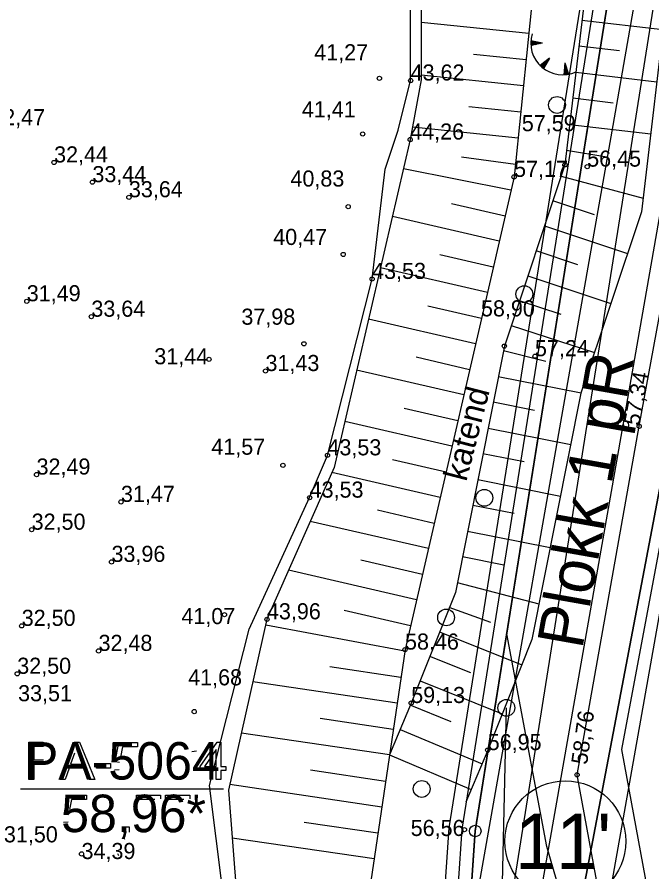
# Model space of a CAD drawing. Extents: x 700746 to 706058, y 6570320 to 6580460.
# Drawn here: x 703241.9 to 703338.5, y 6576222.3 to 6576352.4 of the extents above; entities that cross this region are included whole.
import ezdxf

# ---------------------------------------------------------------- set-up
doc = ezdxf.new("R2010")
doc.units = 0
for name, color, linetype in [('GEOLPUNKT', 7, 'Continuous'), ('HALJASTUS', 7, 'Continuous'), ('illumineerimisjooned', 7, 'Continuous'), ('Kaitsevöönd', 7, 'Continuous'), ('kataster', 7, 'Continuous'), ('KORGUS-EH2000', 7, 'Continuous'), ('KPOHULIIN', 7, 'Continuous'), ('PIIR', 7, 'Continuous'), ('Plokid', 7, 'Continuous'), ('POST', 7, 'Continuous'), ('RELJEEF', 7, 'Continuous'), ('TEE', 7, 'Continuous'), ('Tmaad_maeeraldised_kehtivad', 7, 'Continuous'), ('VEEKOGU', 7, 'Continuous'), ('VTRASS', 7, 'Continuous'), ('VWX2_MV_PLOKK', 7, 'Continuous')]:
    doc.layers.add(name, color=color, linetype=linetype)

msp = doc.modelspace()

# ---------------------------------------------------------------- linework, layer by layer
at = {"layer": 'GEOLPUNKT'}
msp.add_line((703242.38, 6576234.95), (703273.29, 6576234.95), dxfattribs=at)
msp.add_line((703242.38, 6576234.95), (703273.29, 6576234.95), dxfattribs=at)
for points in [[(703243.66, 6576236.35), (703243.66, 6576242.05), (703245.81, 6576242.05)], [(703248.35, 6576236.35), (703250.54, 6576242.05), (703251.36, 6576242.05), (703253.69, 6576236.35), (703252.83, 6576236.35), (703252.17, 6576238.07), (703249.78, 6576238.07), (703249.15, 6576236.35), (703248.35, 6576236.35)], [(703257.44, 6576238.96), (703256.78, 6576239.05), (703257.33, 6576241.98), (703260.17, 6576241.98), (703260.17, 6576241.31), (703257.89, 6576241.31), (703257.59, 6576239.78)], [(703272.18, 6576236.35), (703272.18, 6576237.71), (703269.71, 6576237.71), (703269.71, 6576238.36), (703272.3, 6576242.05), (703272.88, 6576242.05), (703272.88, 6576238.36), (703273.65, 6576238.36), (703273.65, 6576237.71), (703272.88, 6576237.71), (703272.88, 6576236.35), (703272.18, 6576236.35)], [(703245.88, 6576241.38), (703244.42, 6576241.38), (703244.42, 6576239.34)], [(703269.15, 6576240.65), (703268.45, 6576240.59)], [(703272.18, 6576238.36), (703272.18, 6576240.93), (703270.39, 6576238.36), (703272.18, 6576238.36)], [(703244.42, 6576239.34), (703245.89, 6576239.34)], [(703250.62, 6576240.36), (703250, 6576238.69)], [(703250, 6576238.69), (703251.93, 6576238.69), (703251.33, 6576240.27)], [(703245.88, 6576238.67), (703244.42, 6576238.67), (703244.42, 6576236.35), (703243.66, 6576236.35)], [(703253.92, 6576238.06), (703253.92, 6576238.77), (703256.08, 6576238.77), (703256.08, 6576238.06), (703253.92, 6576238.06)], [(703256.66, 6576237.84), (703257.39, 6576237.9)], [(703249.68, 6576230.96), (703249.02, 6576231.05), (703249.58, 6576233.98), (703252.41, 6576233.98), (703252.41, 6576233.31), (703250.14, 6576233.31), (703249.83, 6576231.78)], [(703260.01, 6576233.3), (703260.01, 6576233.98), (703263.7, 6576233.98), (703263.7, 6576233.43)], [(703262.8, 6576233.3), (703260.01, 6576233.3)], [(703264.44, 6576233.3), (703264.44, 6576233.98), (703268.13, 6576233.98), (703268.13, 6576233.43)], [(703267.23, 6576233.3), (703264.44, 6576233.3)], [(703248.9, 6576229.84), (703249.63, 6576229.9)], [(703258.13, 6576228.35), (703258.13, 6576229.14), (703258.93, 6576229.14), (703258.93, 6576228.35)], [(703258.53, 6576228.35), (703258.13, 6576228.35)], [(703261.53, 6576228.35), (703260.81, 6576228.35)], [(703265.95, 6576228.35), (703265.23, 6576228.35)], [(703258.28, 6576227.22), (703258.08, 6576227.52)], [(703257.36, 6576224.76), (703257.17, 6576225.06)]]:
    msp.add_lwpolyline(points, dxfattribs=at)
at = {"layer": 'HALJASTUS'}
for centre in [(703324.05, 6576339.03), (703319.07, 6576310.24), (703312.98, 6576279.23), (703307.16, 6576261.03), (703316.34, 6576247.26), (703303.45, 6576234.92)]:
    msp.add_circle(centre, 1.28, dxfattribs=at)
at = {"layer": 'illumineerimisjooned'}
msp.add_lwpolyline([(703275.45, 6577071.68), (703358.03, 6576531.93), (703309.57, 6576228.79), (703291.69, 6575965.8), (703292.02, 6575933.77), (703296.8, 6575575.06), (702854, 6575511.22), (702839.23, 6575620.77), (702850.34, 6575977.31), (702784.78, 6576064.06), (702784.62, 6576095.83), (702844.43, 6576209.85), (702855.46, 6576267.3), (702846.53, 6576489.41), (702878.89, 6576547.09), (702976.89, 6576643.26), (702915.33, 6577059.56)], dxfattribs=at)
at = {"layer": 'Kaitsevöönd'}
for points in [[(703294.41, 6577068.37), (703355.65, 6576672.76), (703381.7, 6576504.41), (703381.65, 6576500.93), (703378.17, 6576481.28), (703346.05, 6576297.71), (703328.2, 6576197.08), (703364.66, 6576062.16)], [(703344.9, 6576060.57), (703308.07, 6576196.97), (703332.57, 6576335.91), (703361.8, 6576503.07), (703344.23, 6576615.3), (703332.06, 6576694.74), (703304.44, 6576872.64)]]:
    msp.add_lwpolyline(points, dxfattribs=at)
at = {"layer": 'kataster'}
msp.add_lwpolyline([(702852.27, 6575508.89), (702837.26, 6575620.73), (702848.38, 6575976.59), (702782.85, 6576063.35), (702782.57, 6576096.37), (702842.53, 6576210.56), (702853.4, 6576267.5), (702844.46, 6576489.93), (702877.29, 6576548.25), (702974.72, 6576643.9), (702913.57, 6577058.07), (702784.04, 6577102.84), (702746.48, 6577248.7), (702719.69, 6577297.36), (702713.81, 6577334.91), (703089.87, 6577211.79), (703231.53, 6577106.55), (703277.36, 6577072.83), (703360.09, 6576531.99), (703311.6, 6576228.52), (703293.62, 6575965.66), (703298.84, 6575573.29)], close=True, dxfattribs=at)
msp.add_lwpolyline([(703361.97, 6576073.22), (703340.19, 6576155.31), (703330.14, 6576199.75), (703322.48, 6576226.18), (703316.39, 6576258.52), (703360.09, 6576531.99), (703277.36, 6577072.83)], dxfattribs=at)
at = {"layer": 'KORGUS-EH2000'}
for centre in [(703297.01, 6576343.08), (703301.76, 6576342.75), (703294.47, 6576334.62), (703301.7, 6576333.77), (703247.49, 6576330.28), (703325.25, 6576329.91), (703328.64, 6576329.64), (703317.51, 6576328.08), (703253.32, 6576327.28), (703258.88, 6576324.98), (703292.26, 6576323.56), (703291.5, 6576316.28), (703295.9, 6576312.55), (703243.33, 6576309.15), (703253.16, 6576306.8), (703285.52, 6576302.68), (703316.03, 6576302.32), (703271.07, 6576300.31), (703320.69, 6576300.79), (703279.67, 6576298.53), (703336.56, 6576290.12), (703289.1, 6576285.7), (703282.32, 6576284.18), (703244.82, 6576282.77), (703257.67, 6576278.61), (703286.39, 6576279.26), (703244.07, 6576274.38), (703256.23, 6576269.48), (703273.43, 6576261.45), (703279.89, 6576260.74), (703242.56, 6576259.74), (703254.26, 6576255.93), (703300.91, 6576256.13), (703241.88, 6576252.45), (703301.85, 6576248), (703268.82, 6576246.7), (703313.5, 6576240.83), (703327.1, 6576237.07), (703309.96, 6576228.72), (703251.67, 6576225.03)]:
    msp.add_circle(centre, 0.32, dxfattribs=at)
at = {"layer": 'KPOHULIIN'}
msp.add_lwpolyline([(703335.89, 6576129.69), (703317.61, 6576196.56), (703334.12, 6576290.28), (703354.88, 6576408.94), (703371.63, 6576502.97), (703360.78, 6576573.5), (703348.19, 6576656.26), (703310.09, 6576902.12)], dxfattribs=at)
at = {"layer": 'PIIR'}
for centre, radius in [((703325.32, 6576226.96), 9.2), ((703311.6, 6576228.52), 0.88)]:
    msp.add_circle(centre, radius, dxfattribs=at)
at = {"layer": 'Plokid'}
for points in [[(703290.64, 6576959.22), (703356.01, 6576531.94), (703307.59, 6576229.01), (703289.69, 6575965.85), (703290.02, 6575933.75), (703291.51, 6575829.64), (703294.32, 6575609.52), (703294.77, 6575576.79), (703154.76, 6575556.6), (703019.06, 6575536.97), (703053.36, 6575698.14), (703145.59, 6575981.92), (703123.04, 6576234.88), (703120.61, 6576749.6), (703011.59, 6576989.47), (702968.34, 6577084.63), (702917.3, 6577059.88)], [(703294.02, 6575933.8), (703311.73, 6576015.89), (703324.97, 6576203.4), (703382.07, 6576503.63), (703406.89, 6576414.25), (703421.79, 6576214.16), (703443.8, 6575689.35), (703467.14, 6575602.46), (703308.25, 6575608.58), (703295.51, 6575829.03)]]:
    msp.add_lwpolyline(points, dxfattribs=at)
at = {"layer": 'POST'}
for radius in [0.8, 0.0747]:
    msp.add_circle((703334.12, 6576290.28), radius, dxfattribs=at)
at = {"layer": 'RELJEEF'}
for p, q in [((703319.75, 6576349.91), (703303.36, 6576351.59)), ((703327.85, 6576351.96), (703340.18, 6576350.51)), ((703320.04, 6576348.6), (703320.26, 6576348.77)), ((703320.04, 6576348.49), (703320.36, 6576348.75)), ((703320.04, 6576348.39), (703320.46, 6576348.73)), ((703320.04, 6576348.29), (703320.57, 6576348.71)), ((703321.83, 6576348.46), (703320.05, 6576348.81)), ((703320.05, 6576348.7), (703320.15, 6576348.79)), ((703320.05, 6576348.19), (703320.67, 6576348.69)), ((703320.09, 6576348.12), (703320.77, 6576348.67)), ((703320.26, 6576348.15), (703320.88, 6576348.65)), ((703320.43, 6576348.19), (703320.98, 6576348.63)), ((703320.6, 6576348.22), (703321.08, 6576348.61)), ((703320.77, 6576348.25), (703321.18, 6576348.59)), ((703320.94, 6576348.29), (703321.29, 6576348.57)), ((703321.83, 6576348.46), (703320.05, 6576348.11)), ((703321.11, 6576348.32), (703321.39, 6576348.55)), ((703321.27, 6576348.35), (703321.49, 6576348.53)), ((703321.44, 6576348.39), (703321.6, 6576348.51)), ((703321.61, 6576348.42), (703321.7, 6576348.49)), ((703333.55, 6576347.27), (703327.38, 6576347.99)), ((703311.35, 6576346.75), (703319.34, 6576345.93)), ((703322.9, 6576346.16), (703321.47, 6576345.03)), ((703322.9, 6576346.16), (703322, 6576344.58)), ((703322.7, 6576345.81), (703322.71, 6576346.01)), ((703322.79, 6576345.96), (703322.79, 6576346.07)), ((703321.55, 6576344.96), (703321.55, 6576345.09)), ((703321.63, 6576344.89), (703321.64, 6576345.16)), ((703321.7, 6576344.82), (703321.72, 6576345.23)), ((703321.78, 6576344.75), (703321.8, 6576345.29)), ((703321.86, 6576344.69), (703321.88, 6576345.36)), ((703321.94, 6576344.63), (703321.97, 6576345.42)), ((703322.02, 6576344.61), (703322.05, 6576345.49)), ((703322.1, 6576344.76), (703322.13, 6576345.55)), ((703322.19, 6576344.91), (703322.21, 6576345.62)), ((703322.27, 6576345.06), (703322.3, 6576345.68)), ((703322.36, 6576345.21), (703322.38, 6576345.75)), ((703322.44, 6576345.36), (703322.46, 6576345.81)), ((703322.53, 6576345.51), (703322.54, 6576345.88)), ((703322.62, 6576345.66), (703322.62, 6576345.94)), ((703325.24, 6576345.44), (703325.1, 6576343.63)), ((703325.62, 6576344.24), (703325.18, 6576344.68)), ((703325.57, 6576344.4), (703325.19, 6576344.78)), ((703325.52, 6576344.57), (703325.2, 6576344.89)), ((703325.41, 6576344.9), (703325.21, 6576345.1)), ((703325.47, 6576344.73), (703325.21, 6576344.99)), ((703325.36, 6576345.06), (703325.22, 6576345.2)), ((703325.31, 6576345.23), (703325.23, 6576345.31)), ((703325.24, 6576345.44), (703325.79, 6576343.71)), ((703318.93, 6576341.95), (703303.35, 6576343.55)), ((703325.21, 6576343.64), (703325.11, 6576343.73)), ((703325.31, 6576343.65), (703325.12, 6576343.84)), ((703325.42, 6576343.66), (703325.13, 6576343.94)), ((703325.62, 6576343.68), (703325.14, 6576344.15)), ((703325.52, 6576343.67), (703325.14, 6576344.05)), ((703325.72, 6576343.7), (703325.15, 6576344.26)), ((703325.78, 6576343.75), (703325.16, 6576344.36)), ((703325.68, 6576344.08), (703325.17, 6576344.57)), ((703325.73, 6576343.91), (703325.17, 6576344.47)), ((703326.92, 6576344.02), (703339.24, 6576342.57)), ((703332.61, 6576339.32), (703326.45, 6576340.05)), ((703310.64, 6576338.78), (703318.52, 6576337.97)), ((703318.11, 6576333.99), (703302.04, 6576335.64)), ((703325.98, 6576336.07), (703338.31, 6576334.62)), ((703331.64, 6576331.09), (703325.51, 6576332.1)), ((703309.52, 6576331.12), (703317.71, 6576330.01)), ((703317.04, 6576326.07), (703300.67, 6576329.33)), ((703324.69, 6576328.21), (703337.15, 6576324.82)), ((703308.01, 6576324.05), (703316.14, 6576322.18)), ((703329.74, 6576322.3), (703323.42, 6576324.42)), ((703315.25, 6576318.28), (703298.98, 6576322.03)), ((703322.15, 6576320.62), (703334.79, 6576316.4)), ((703306.21, 6576316.26), (703314.35, 6576314.38)), ((703327.2, 6576314.72), (703320.88, 6576316.83)), ((703313.45, 6576310.48), (703297.17, 6576314.24)), ((703319.62, 6576313.03), (703332.25, 6576308.81)), ((703304.4, 6576308.46), (703312.55, 6576306.59)), ((703324.67, 6576307.13), (703318.35, 6576309.24)), ((703311.65, 6576302.69), (703295.35, 6576306.45)), ((703317.08, 6576305.45), (703329.76, 6576301.36)), ((703302.6, 6576300.67), (703310.75, 6576298.79)), ((703322.33, 6576300), (703315.9, 6576301.63)), ((703309.85, 6576294.89), (703293.54, 6576298.65)), ((703315.11, 6576297.71), (703327.7, 6576295.2)), ((703300.8, 6576292.88), (703308.95, 6576291)), ((703320.62, 6576292.53), (703314.33, 6576293.79)), ((703308.05, 6576287.1), (703291.73, 6576290.86)), ((703313.55, 6576289.86), (703326.13, 6576287.36)), ((703298.99, 6576285.08), (703307.15, 6576283.2)), ((703319.06, 6576284.69), (703312.77, 6576285.94)), ((703306.25, 6576279.3), (703289.77, 6576283.1)), ((703311.99, 6576282.02), (703324.57, 6576279.51)), ((703296.74, 6576277.39), (703305.36, 6576275.4)), ((703317.5, 6576276.84), (703311.21, 6576278.09)), ((703304.46, 6576271.51), (703286.48, 6576275.65)), ((703310.43, 6576274.17), (703323.01, 6576271.67)), ((703294.2, 6576269.77), (703303.56, 6576267.61)), ((703315.94, 6576268.99), (703309.65, 6576270.25)), ((703302.66, 6576263.71), (703283.19, 6576268.2)), ((703308.87, 6576266.32), (703321.3, 6576263.11)), ((703291.64, 6576262.12), (703301.76, 6576259.81)), ((703313.97, 6576260.26), (703307.65, 6576262.53)), ((703300.88, 6576255.91), (703279.7, 6576259.87)), ((703306.17, 6576258.82), (703318.69, 6576253.82)), ((703310.94, 6576252.6), (703304.68, 6576255.1)), ((703289.46, 6576253.56), (703300.29, 6576251.96)), ((703299.7, 6576248), (703277.76, 6576251.25)), ((703303.2, 6576251.39), (703315.71, 6576246.38)), ((703307.95, 6576245.12), (703301.71, 6576247.67)), ((703288, 6576245.69), (703299.12, 6576244.04)), ((703298.53, 6576240.09), (703276, 6576243.42)), ((703300.17, 6576243.98), (703312.63, 6576238.76)), ((703298.53, 6576240.09), (703311, 6576234.86)), ((703286.54, 6576237.82), (703297.95, 6576236.13)), ((703297.36, 6576232.17), (703274.25, 6576235.6)), ((703285.54, 6576229.88), (703296.77, 6576228.22)), ((703296.19, 6576224.26), (703274.62, 6576227.45))]:
    msp.add_line(p, q, dxfattribs=at)
for points in [[(703294.98, 6576976.89), (703298.01, 6576952.03), (703308.39, 6576903.66), (703310.22, 6576881.63), (703320.05, 6576759.49), (703327.51, 6576726.85), (703331.13, 6576688.4), (703329.02, 6576656.14), (703332.85, 6576644.87), (703338.24, 6576624.53), (703339.69, 6576609.71), (703342.98, 6576573.75), (703350.64, 6576557.99), (703360.73, 6576522.36), (703358.27, 6576513.58), (703356.22, 6576500.08), (703348.18, 6576445.4), (703346.58, 6576371.38), (703340.93, 6576356.93), (703336.91, 6576322.74), (703327.68, 6576295.15), (703320.22, 6576257.66), (703313.5, 6576240.83), (703310.18, 6576232.92)], [(703287.76, 6576969.22), (703301.66, 6576878.37), (703308.4, 6576766.66), (703315.86, 6576734.02), (703319.48, 6576695.57), (703324.84, 6576668.62), (703325.06, 6576655.25), (703326.59, 6576631.7), (703333, 6576614.8), (703334.36, 6576592.7), (703343.18, 6576565.16), (703350.63, 6576529.53), (703350.13, 6576518.58), (703344.56, 6576507.25), (703336.53, 6576452.57), (703334.93, 6576378.55), (703329.28, 6576364.1), (703325.25, 6576329.91), (703316.03, 6576302.32), (703308.57, 6576264.82), (703301.85, 6576248), (703298.53, 6576240.09)], [(703290.63, 6576796.53), (703294.18, 6576752.74), (703301.26, 6576735.92), (703310.06, 6576699.51), (703308, 6576689.73), (703309.22, 6576677.55), (703319.19, 6576654.75), (703329.82, 6576561.84), (703330.05, 6576553.02), (703327.91, 6576515.52), (703314.12, 6576455.74), (703313.17, 6576416.87), (703317.14, 6576393.59), (703321.81, 6576369.95), (703317.51, 6576328.08), (703300.91, 6576256.13), (703281.53, 6576125.34), (703279.97, 6576118.46), (703265.55, 6576092.54), (703268.13, 6576079.38)], [(703303.38, 6576364.56), (703303.35, 6576342.85), (703301.7, 6576333.77), (703290.11, 6576283.87), (703279.89, 6576260.74), (703274.06, 6576234.76), (703275.32, 6576218.35), (703275.49, 6576205.75), (703269.41, 6576189.26), (703271.94, 6576176.58), (703267.72, 6576162.54), (703268.7, 6576147.32), (703268.71, 6576122.58), (703265.25, 6576111.59), (703260.9, 6576100.04), (703247.69, 6576093.18), (703243.06, 6576086.17)], [(703343.84, 6576081.11), (703335.7, 6576108.2), (703330.71, 6576134.71), (703326.75, 6576152.5), (703322.22, 6576165.18), (703315.6, 6576173.43), (703312.69, 6576179.01), (703314.2, 6576192.38), (703315.77, 6576220.64), (703316.34, 6576247.26)]]:
    msp.add_lwpolyline(points, dxfattribs=at)
msp.add_arc((703324.88, 6576348.47), 4.84, 163.4234, 295.1745, dxfattribs=at)
at = {"layer": 'TEE'}
for points in [[(703352.19, 6576141.74), (703333.89, 6576240.91), (703343.28, 6576291), (703349.94, 6576325.8), (703355.47, 6576356.51), (703364.51, 6576409.39), (703371.49, 6576445.79), (703377.05, 6576478.47), (703380.32, 6576501.7), (703378.7, 6576535.4), (703372.61, 6576579.28), (703366.54, 6576617.95), (703359.6, 6576660.21), (703326.86, 6576887.21), (703316.48, 6576960.36), (703310.76, 6576994.71), (703303.15, 6577040.42), (703296.06, 6577071.1), (703290.16, 6577081.59), (703186.34, 6577164.98)], [(703345.4, 6576137.9), (703327.1, 6576237.07), (703336.56, 6576290.12), (703343.25, 6576326.51), (703348.81, 6576358.13), (703358.18, 6576409.8), (703364.65, 6576448.18), (703369.91, 6576476.49), (703373.71, 6576502.52), (703371.54, 6576534.25), (703365.82, 6576575.44), (703359.75, 6576614.11), (703352.81, 6576656.37), (703320.07, 6576883.37), (703309.69, 6576956.52), (703303.97, 6576990.87), (703296.36, 6577036.58), (703289.27, 6577067.26), (703283.37, 6577077.75), (703179.55, 6577161.14)]]:
    msp.add_lwpolyline(points, dxfattribs=at)
at = {"layer": 'Tmaad_maeeraldised_kehtivad'}
msp.add_lwpolyline([(703277.3, 6577072.8), (703360.06, 6576531.93), (703311.56, 6576228.56), (703293.69, 6575965.74), (703294.02, 6575933.8), (703298.82, 6575573.33), (702852.29, 6575508.95), (702837.23, 6575620.66), (702848.32, 6575976.66), (702782.78, 6576063.39), (702782.61, 6576096.32), (702842.53, 6576210.52), (702853.45, 6576267.45), (702844.51, 6576489.89), (702877.28, 6576548.31), (702974.76, 6576643.97), (702913.53, 6577058.07)], dxfattribs=at)
at = {"layer": 'VEEKOGU'}
msp.add_lwpolyline([(703242.36, 6576086.56), (703246.24, 6576093.9), (703260.25, 6576102.13), (703264.13, 6576113.28), (703267, 6576122.75), (703266.58, 6576147.78), (703264.89, 6576162.72), (703269.88, 6576177.55), (703266.92, 6576189.55), (703273.59, 6576206.89), (703273.17, 6576219.29), (703271.14, 6576235.47), (703277.19, 6576259.24), (703286.39, 6576279.26), (703289.1, 6576285.7), (703295.9, 6576312.55), (703297.89, 6576329.27), (703299.86, 6576335.18), (703301.76, 6576342.75), (703301.78, 6576365.92)], dxfattribs=at)
msp.add_lwpolyline([(703242.36, 6576086.56), (703246.24, 6576093.9), (703260.25, 6576102.13), (703264.13, 6576113.28), (703267, 6576122.75), (703266.58, 6576147.78), (703264.89, 6576162.72), (703269.88, 6576177.55), (703266.92, 6576189.55), (703273.59, 6576206.89), (703273.17, 6576219.29), (703271.14, 6576235.47), (703277.19, 6576259.24), (703286.39, 6576279.26), (703289.1, 6576285.7), (703295.9, 6576312.55), (703297.89, 6576329.27), (703299.86, 6576335.18), (703301.76, 6576342.75), (703301.78, 6576365.92)], dxfattribs=at)
at = {"layer": 'VTRASS'}
msp.add_lwpolyline([(703383.92, 6576537.61), (703365.97, 6576507.97), (703351.39, 6576433.02), (703345.21, 6576395.16), (703316.4, 6576213.76)], dxfattribs=at)
at = {"layer": 'VWX2_MV_PLOKK'}
for points in [[(703044.07, 6577449.05), (703125.37, 6577441.7), (703167.08, 6577172.26), (703170.22, 6577152.1), (703231.53, 6577106.55), (703277.36, 6577072.83), (703360.09, 6576531.99), (703311.6, 6576228.52), (703293.62, 6575965.66), (703294.04, 6575933.77), (703295.43, 6575829.7), (703298.36, 6575609.6), (703298.84, 6575573.29), (703155.29, 6575552.59), (703145.59, 6575981.92), (703123.04, 6576234.88), (703120.61, 6576749.6), (703011.59, 6576989.47), (703015.74, 6577110.88), (702996.73, 6577210.32)], [(703170.54, 6577151.86), (703296.17, 6577067.83), (703382.07, 6576503.63), (703324.97, 6576203.4), (703311.73, 6576015.89), (703294.04, 6575933.77), (703293.62, 6575965.66), (703311.6, 6576228.52), (703360.09, 6576531.99), (703277.36, 6577072.83), (703231.53, 6577106.55)], [(703443.86, 6575689.39), (703467.13, 6575602.53), (703308.24, 6575608.65), (703295.44, 6575828.99), (703294.04, 6575933.77), (703311.73, 6576015.89), (703324.97, 6576203.33), (703382.07, 6576503.63), (703406.94, 6576414.24), (703421.77, 6576214.18)]]:
    msp.add_lwpolyline(points, close=True, dxfattribs=at)
msp.add_lwpolyline([(703187.67, 6576999.67), (703190.39, 6576656.32), (703340.88, 6576657.54), (703360.09, 6576531.99), (703311.6, 6576228.52), (703293.62, 6575965.66), (703294.04, 6575933.77), (703295.43, 6575829.7), (703298.36, 6575609.6), (703298.84, 6575573.29), (703155.29, 6575552.59), (703018.17, 6575532.81), (703053.36, 6575698.14), (703145.59, 6575981.92), (703123.04, 6576234.88), (703120.61, 6576749.6), (703011.59, 6576989.47)], dxfattribs=at)
msp.add_lwpolyline([(703187.67, 6576999.67), (703190.39, 6576656.32), (703340.88, 6576657.54), (703360.09, 6576531.99), (703311.6, 6576228.52), (703293.62, 6575965.66), (703294.04, 6575933.77), (703295.43, 6575829.7), (703298.36, 6575609.6), (703298.84, 6575573.29), (703155.29, 6575552.59), (703018.17, 6575532.81), (703053.36, 6575698.14), (703145.59, 6575981.92), (703123.04, 6576234.88), (703120.61, 6576749.6), (703011.59, 6576989.47)], dxfattribs=at)

# ---------------------------------------------------------------- texts
at = {"layer": 'GEOLPUNKT'}
for s, p in [('PA-5064', (703243.05, 6576236.35)), ('58,96*', (703248.57, 6576228.35))]:
    msp.add_text(s, height=5.7, dxfattribs=at).set_placement(p)
at = {"layer": 'KORGUS-EH2000'}
for s, p in [('41,27 ', (703287.09, 6576345.83)), ('43,62 ', (703301.76, 6576342.75)), ('41,41 ', (703285.21, 6576337.15)), ('32,47 ', (703237.92, 6576335.95)), ('57,59 ', (703318.69, 6576335.04)), ('44,26 ', (703301.7, 6576333.77)), ('32,44 ', (703247.49, 6576330.28)), ('56,45 ', (703328.64, 6576329.64)), ('57,17 ', (703317.51, 6576328.08)), ('33,44 ', (703253.32, 6576327.28)), ('40,83 ', (703283.47, 6576326.61)), ('33,64 ', (703258.88, 6576324.98)), ('40,47 ', (703280.85, 6576317.72)), ('43,53 ', (703295.9, 6576312.55)), ('31,49 ', (703243.33, 6576309.15)), ('33,64 ', (703253.16, 6576306.8)), ('58,90 ', (703312.47, 6576306.85)), ('37,98 ', (703276, 6576305.58)), ('57,24 ', (703320.69, 6576300.79)), ('31,44 ', (703262.74, 6576299.56)), ('31,43 ', (703279.67, 6576298.53)), ('41,57 ', (703271.42, 6576285.79)), ('43,53 ', (703289.1, 6576285.7)), ('32,49 ', (703244.82, 6576282.77)), ('31,47 ', (703257.67, 6576278.61)), ('43,53 ', (703286.39, 6576279.26)), ('32,50 ', (703244.07, 6576274.38)), ('33,96 ', (703256.23, 6576269.48)), ('43,96 ', (703279.89, 6576260.74)), ('32,50 ', (703242.56, 6576259.74)), ('41,07 ', (703266.87, 6576260.01)), ('32,48 ', (703254.26, 6576255.93)), ('58,46 ', (703300.91, 6576256.13)), ('32,50 ', (703241.88, 6576252.45)), ('41,68 ', (703267.9, 6576250.69)), ('33,51 ', (703242.01, 6576248.27)), ('59,13 ', (703301.85, 6576248)), ('56,95 ', (703313.5, 6576240.83)), ('56,56 ', (703301.77, 6576227.76)), ('31,50 ', (703239.85, 6576226.79)), ('34,39 ', (703251.67, 6576224.25))]:
    msp.add_text(s, height=2.45, dxfattribs=at).set_placement(p)
for s, rotation, p in [('57,34 ', 79.3068, (703336.56, 6576290.12)), ('58,76 ', 82.2134, (703328.62, 6576238.54))]:
    msp.add_text(s, height=2.45, rotation=rotation, dxfattribs=at).set_placement(p)
at = {"layer": 'PIIR'}
msp.add_text("11'", height=8.4, dxfattribs=at).set_placement((703317.66, 6576222.76))
at = {"layer": 'Plokid'}
msp.add_text('Plokk 1 pR', height=7, rotation=79.9389, dxfattribs=at).set_placement((703327.88, 6576256.05))
at = {"layer": 'RELJEEF'}
msp.add_text('katend', height=3.6, rotation=75.5665, dxfattribs=at).set_placement((703310.23, 6576281.59))

doc.saveas('drawing.dxf')
